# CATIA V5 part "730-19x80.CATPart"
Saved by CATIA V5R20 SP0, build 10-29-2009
Part number: 730-19x80
Definition: NONE
Nomenclature: 730-19x80
Source: Unknown
Description: 730-19x80
Bounding box of the stored display mesh (mm): x -12.441 to 12.441, y -11.818 to 11.818, z 0 to 80
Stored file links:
  C:\Users\Utente\Desktop\IO LAVORO\3D X SITO CF\X SITO\730\730-19x80.CATPart
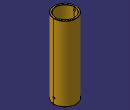
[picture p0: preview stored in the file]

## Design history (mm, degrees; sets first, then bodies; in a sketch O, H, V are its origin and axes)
Body1 "730-19x80" (main body)
  Solid1: solid without history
